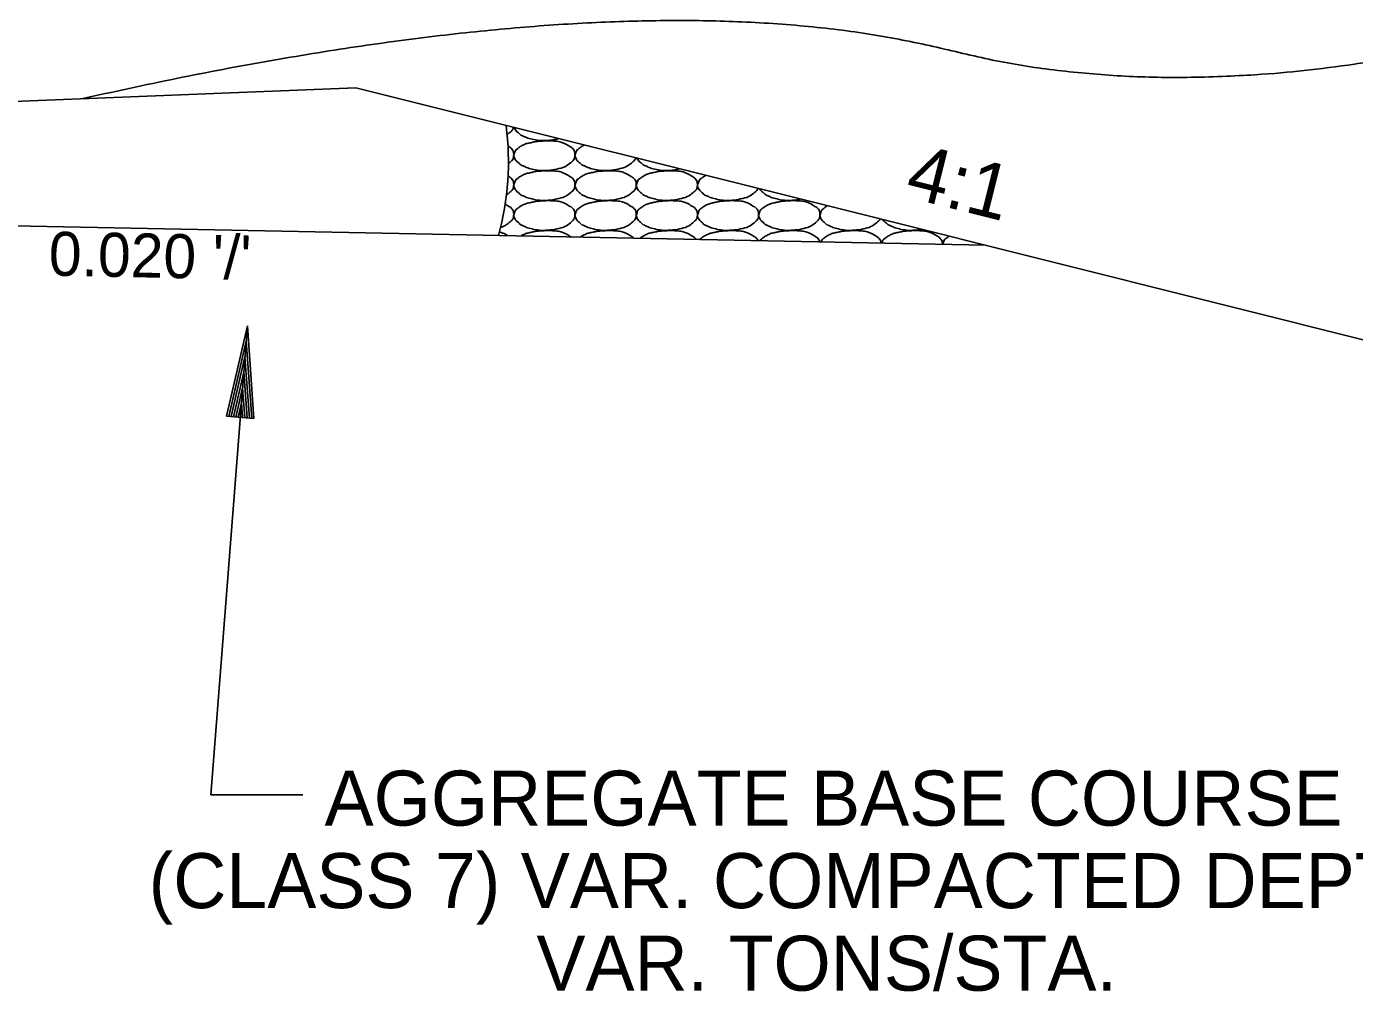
# Model space of a CAD drawing. Extents: x 2263886 to 2266026, y -3122850 to -3121850.
# Drawn here: x 2265622.12 to 2265636.6, y -3122515.03 to -3122504.51 of the extents above; entities that cross this region are included whole.
import ezdxf

# ---------------------------------------------------------------- set-up
doc = ezdxf.new("R2010")
doc.units = 0
doc.layers.add('R_Border Prem', color=7, linetype='Continuous')

msp = doc.modelspace()

# ---------------------------------------------------------------- linework, layer by layer
at = {"layer": 'R_Border Prem'}
for p, q in [((2265619.716, -3122505.418), (2265625.711, -3122505.178)), ((2265631.356, -3122506.589), (2265625.711, -3122505.178)), ((2265619.773, -3122506.638), (2265632.576, -3122506.894)), ((2265637.711, -3122508.178), (2265631.356, -3122506.589)), ((2265624.528, -3122507.774), (2265624.131, -3122512.886)), ((2265624.301, -3122508.759), (2265624.528, -3122507.774)), ((2265624.6, -3122508.782), (2265624.528, -3122507.774)), ((2265624.326, -3122508.761), (2265624.515, -3122507.94)), ((2265624.575, -3122508.78), (2265624.515, -3122507.94)), ((2265624.352, -3122508.763), (2265624.502, -3122508.112)), ((2265624.55, -3122508.778), (2265624.502, -3122508.112)), ((2265624.377, -3122508.765), (2265624.489, -3122508.278)), ((2265624.525, -3122508.777), (2265624.489, -3122508.278)), ((2265624.402, -3122508.767), (2265624.476, -3122508.447)), ((2265624.5, -3122508.775), (2265624.476, -3122508.447)), ((2265624.427, -3122508.769), (2265624.463, -3122508.613)), ((2265624.474, -3122508.773), (2265624.463, -3122508.613)), ((2265624.301, -3122508.759), (2265624.6, -3122508.782)), ((2265624.131, -3122512.886), (2265625.131, -3122512.886))]:
    msp.add_line(p, q, dxfattribs=at)
msp.add_arc((2265624.375, -3122505.984), 3, 344.4638, 7.5551, dxfattribs=at)
for points, degree in [([(2265622.714, -3122505.298), (2265628.831, -3122503.917), (2265635.52, -3122505.616), (2265640.146, -3122504.036)], 2), ([(2265627.36, -3122505.688), (2265627.369, -3122505.681), (2265627.393, -3122505.662), (2265627.421, -3122505.638), (2265627.428, -3122505.615), (2265627.429, -3122505.61)], 3), ([(2265627.439, -3122505.612), (2265627.442, -3122505.62), (2265627.449, -3122505.635), (2265627.467, -3122505.657), (2265627.492, -3122505.672), (2265627.507, -3122505.695), (2265627.534, -3122505.7), (2265627.569, -3122505.721), (2265627.631, -3122505.737), (2265627.711, -3122505.754), (2265627.806, -3122505.752), (2265627.875, -3122505.742), (2265627.913, -3122505.734), (2265627.919, -3122505.732)], 3), ([(2265627.459, -3122505.85), (2265627.453, -3122505.856), (2265627.446, -3122505.871), (2265627.439, -3122505.894), (2265627.429, -3122505.915), (2265627.439, -3122505.939), (2265627.448, -3122505.96), (2265627.467, -3122505.983), (2265627.492, -3122505.998), (2265627.507, -3122506.021), (2265627.534, -3122506.026), (2265627.569, -3122506.047), (2265627.631, -3122506.063), (2265627.711, -3122506.08), (2265627.806, -3122506.079), (2265627.904, -3122506.065), (2265627.994, -3122506.041), (2265628.053, -3122505.995), (2265628.095, -3122505.959), (2265628.1, -3122505.92), (2265628.101, -3122505.887), (2265628.093, -3122505.859), (2265628.076, -3122505.839), (2265628.059, -3122505.823), (2265628.033, -3122505.812), (2265628.011, -3122505.793), (2265627.978, -3122505.782), (2265627.938, -3122505.762), (2265627.872, -3122505.758), (2265627.801, -3122505.753), (2265627.731, -3122505.76), (2265627.676, -3122505.76), (2265627.63, -3122505.774), (2265627.584, -3122505.781), (2265627.541, -3122505.796), (2265627.502, -3122505.818), (2265627.476, -3122505.839), (2265627.458, -3122505.851), (2265627.453, -3122505.856)], 3), ([(2265627.374, -3122506.003), (2265627.379, -3122506), (2265627.398, -3122505.984), (2265627.427, -3122505.959), (2265627.432, -3122505.92), (2265627.433, -3122505.887), (2265627.425, -3122505.859), (2265627.408, -3122505.839), (2265627.391, -3122505.823), (2265627.377, -3122505.816), (2265627.369, -3122505.811)], 3), ([(2265628.127, -3122505.85), (2265628.121, -3122505.856), (2265628.113, -3122505.871), (2265628.107, -3122505.894), (2265628.097, -3122505.915), (2265628.107, -3122505.939), (2265628.116, -3122505.96), (2265628.135, -3122505.983), (2265628.16, -3122505.998), (2265628.175, -3122506.021), (2265628.202, -3122506.026), (2265628.236, -3122506.047), (2265628.299, -3122506.063), (2265628.379, -3122506.08), (2265628.474, -3122506.079), (2265628.572, -3122506.065), (2265628.662, -3122506.041), (2265628.721, -3122505.995), (2265628.754, -3122505.966), (2265628.762, -3122505.946), (2265628.763, -3122505.943)], 3), ([(2265628.199, -3122505.802), (2265628.19, -3122505.806), (2265628.168, -3122505.819), (2265628.144, -3122505.839), (2265628.126, -3122505.851), (2265628.121, -3122505.856)], 3), ([(2265627.459, -3122506.177), (2265627.453, -3122506.182), (2265627.446, -3122506.197), (2265627.439, -3122506.22), (2265627.429, -3122506.241), (2265627.439, -3122506.265), (2265627.448, -3122506.286), (2265627.467, -3122506.31), (2265627.492, -3122506.324), (2265627.507, -3122506.347), (2265627.534, -3122506.353), (2265627.569, -3122506.373), (2265627.631, -3122506.389), (2265627.711, -3122506.406), (2265627.806, -3122506.405), (2265627.904, -3122506.391), (2265627.994, -3122506.367), (2265628.053, -3122506.321), (2265628.095, -3122506.285), (2265628.1, -3122506.246), (2265628.101, -3122506.213), (2265628.093, -3122506.185), (2265628.076, -3122506.165), (2265628.059, -3122506.149), (2265628.033, -3122506.138), (2265628.011, -3122506.12), (2265627.978, -3122506.108), (2265627.938, -3122506.088), (2265627.872, -3122506.084), (2265627.801, -3122506.079), (2265627.731, -3122506.086), (2265627.676, -3122506.086), (2265627.63, -3122506.1), (2265627.584, -3122506.107), (2265627.541, -3122506.123), (2265627.502, -3122506.144), (2265627.476, -3122506.165), (2265627.458, -3122506.177), (2265627.453, -3122506.183)], 3), ([(2265628.127, -3122506.177), (2265628.121, -3122506.182), (2265628.113, -3122506.197), (2265628.107, -3122506.22), (2265628.097, -3122506.241), (2265628.107, -3122506.265), (2265628.116, -3122506.286), (2265628.135, -3122506.31), (2265628.16, -3122506.324), (2265628.175, -3122506.347), (2265628.202, -3122506.353), (2265628.236, -3122506.373), (2265628.299, -3122506.389), (2265628.379, -3122506.406), (2265628.474, -3122506.405), (2265628.572, -3122506.391), (2265628.662, -3122506.367), (2265628.721, -3122506.321), (2265628.763, -3122506.285), (2265628.768, -3122506.246), (2265628.768, -3122506.213), (2265628.761, -3122506.185), (2265628.744, -3122506.165), (2265628.727, -3122506.149), (2265628.701, -3122506.138), (2265628.678, -3122506.12), (2265628.646, -3122506.108), (2265628.606, -3122506.088), (2265628.54, -3122506.084), (2265628.469, -3122506.079), (2265628.399, -3122506.086), (2265628.344, -3122506.086), (2265628.297, -3122506.1), (2265628.252, -3122506.107), (2265628.209, -3122506.123), (2265628.17, -3122506.144), (2265628.144, -3122506.165), (2265628.126, -3122506.177), (2265628.121, -3122506.183)], 3), ([(2265628.795, -3122506.177), (2265628.789, -3122506.182), (2265628.781, -3122506.197), (2265628.775, -3122506.22), (2265628.764, -3122506.241), (2265628.775, -3122506.265), (2265628.784, -3122506.286), (2265628.803, -3122506.31), (2265628.828, -3122506.324), (2265628.843, -3122506.347), (2265628.87, -3122506.353), (2265628.904, -3122506.373), (2265628.967, -3122506.389), (2265629.047, -3122506.406), (2265629.142, -3122506.405), (2265629.24, -3122506.391), (2265629.33, -3122506.367), (2265629.389, -3122506.321), (2265629.431, -3122506.285), (2265629.436, -3122506.246), (2265629.436, -3122506.213), (2265629.428, -3122506.185), (2265629.412, -3122506.165), (2265629.394, -3122506.149), (2265629.368, -3122506.138), (2265629.346, -3122506.12), (2265629.314, -3122506.108), (2265629.273, -3122506.088), (2265629.207, -3122506.084), (2265629.137, -3122506.079), (2265629.066, -3122506.086), (2265629.012, -3122506.086), (2265628.965, -3122506.1), (2265628.92, -3122506.107), (2265628.877, -3122506.123), (2265628.838, -3122506.144), (2265628.812, -3122506.165), (2265628.794, -3122506.177), (2265628.789, -3122506.183)], 3), ([(2265628.778, -3122505.947), (2265628.78, -3122505.952), (2265628.787, -3122505.964), (2265628.803, -3122505.983), (2265628.828, -3122505.998), (2265628.843, -3122506.021), (2265628.87, -3122506.026), (2265628.904, -3122506.047), (2265628.967, -3122506.063), (2265629.047, -3122506.08), (2265629.142, -3122506.079), (2265629.205, -3122506.069), (2265629.238, -3122506.062), (2265629.238, -3122506.062)], 3), ([(2265627.354, -3122506.344), (2265627.365, -3122506.337), (2265627.392, -3122506.316), (2265627.427, -3122506.285), (2265627.432, -3122506.246), (2265627.433, -3122506.213), (2265627.425, -3122506.185), (2265627.408, -3122506.165), (2265627.392, -3122506.15), (2265627.377, -3122506.142), (2265627.37, -3122506.138)], 3), ([(2265629.463, -3122506.177), (2265629.457, -3122506.182), (2265629.449, -3122506.197), (2265629.443, -3122506.22), (2265629.432, -3122506.241), (2265629.442, -3122506.265), (2265629.452, -3122506.286), (2265629.471, -3122506.31), (2265629.495, -3122506.324), (2265629.511, -3122506.347), (2265629.538, -3122506.353), (2265629.572, -3122506.373), (2265629.634, -3122506.389), (2265629.715, -3122506.406), (2265629.81, -3122506.405), (2265629.908, -3122506.391), (2265629.998, -3122506.367), (2265630.057, -3122506.321), (2265630.087, -3122506.295), (2265630.096, -3122506.277), (2265630.096, -3122506.277)], 3), ([(2265629.524, -3122506.134), (2265629.519, -3122506.136), (2265629.501, -3122506.147), (2265629.479, -3122506.165), (2265629.462, -3122506.177), (2265629.457, -3122506.183)], 3), ([(2265630.118, -3122506.282), (2265630.119, -3122506.284), (2265630.124, -3122506.293), (2265630.139, -3122506.31), (2265630.163, -3122506.324), (2265630.179, -3122506.347), (2265630.206, -3122506.353), (2265630.24, -3122506.373), (2265630.302, -3122506.389), (2265630.383, -3122506.406), (2265630.472, -3122506.405), (2265630.53, -3122506.397), (2265630.557, -3122506.392)], 3), ([(2265627.288, -3122506.7), (2265627.302, -3122506.695), (2265627.34, -3122506.682), (2265627.385, -3122506.647), (2265627.427, -3122506.611), (2265627.432, -3122506.573), (2265627.433, -3122506.539), (2265627.425, -3122506.511), (2265627.408, -3122506.492), (2265627.391, -3122506.475), (2265627.365, -3122506.464), (2265627.35, -3122506.448), (2265627.339, -3122506.445), (2265627.339, -3122506.444)], 3), ([(2265627.459, -3122506.503), (2265627.453, -3122506.508), (2265627.446, -3122506.523), (2265627.439, -3122506.547), (2265627.429, -3122506.567), (2265627.439, -3122506.591), (2265627.448, -3122506.612), (2265627.467, -3122506.636), (2265627.492, -3122506.651), (2265627.507, -3122506.674), (2265627.534, -3122506.679), (2265627.569, -3122506.699), (2265627.631, -3122506.716), (2265627.711, -3122506.733), (2265627.806, -3122506.731), (2265627.904, -3122506.718), (2265627.994, -3122506.694), (2265628.053, -3122506.647), (2265628.095, -3122506.611), (2265628.1, -3122506.573), (2265628.101, -3122506.539), (2265628.093, -3122506.511), (2265628.076, -3122506.492), (2265628.059, -3122506.475), (2265628.033, -3122506.464), (2265628.011, -3122506.446), (2265627.978, -3122506.434), (2265627.938, -3122506.414), (2265627.872, -3122506.41), (2265627.801, -3122506.405), (2265627.731, -3122506.412), (2265627.676, -3122506.413), (2265627.63, -3122506.426), (2265627.584, -3122506.433), (2265627.541, -3122506.449), (2265627.502, -3122506.47), (2265627.476, -3122506.491), (2265627.458, -3122506.503), (2265627.453, -3122506.509)], 3), ([(2265628.127, -3122506.503), (2265628.121, -3122506.508), (2265628.113, -3122506.523), (2265628.107, -3122506.547), (2265628.097, -3122506.567), (2265628.107, -3122506.591), (2265628.116, -3122506.612), (2265628.135, -3122506.636), (2265628.16, -3122506.651), (2265628.175, -3122506.674), (2265628.202, -3122506.679), (2265628.236, -3122506.699), (2265628.299, -3122506.716), (2265628.379, -3122506.733), (2265628.474, -3122506.731), (2265628.572, -3122506.718), (2265628.662, -3122506.694), (2265628.721, -3122506.647), (2265628.763, -3122506.611), (2265628.768, -3122506.573), (2265628.768, -3122506.539), (2265628.761, -3122506.511), (2265628.744, -3122506.492), (2265628.727, -3122506.475), (2265628.701, -3122506.464), (2265628.678, -3122506.446), (2265628.646, -3122506.434), (2265628.606, -3122506.414), (2265628.54, -3122506.41), (2265628.469, -3122506.405), (2265628.399, -3122506.412), (2265628.344, -3122506.413), (2265628.297, -3122506.426), (2265628.252, -3122506.433), (2265628.209, -3122506.449), (2265628.17, -3122506.47), (2265628.144, -3122506.491), (2265628.126, -3122506.503), (2265628.121, -3122506.509)], 3), ([(2265628.795, -3122506.503), (2265628.789, -3122506.508), (2265628.781, -3122506.523), (2265628.775, -3122506.547), (2265628.764, -3122506.567), (2265628.775, -3122506.591), (2265628.784, -3122506.612), (2265628.803, -3122506.636), (2265628.828, -3122506.651), (2265628.843, -3122506.674), (2265628.87, -3122506.679), (2265628.904, -3122506.699), (2265628.967, -3122506.716), (2265629.047, -3122506.733), (2265629.142, -3122506.731), (2265629.24, -3122506.718), (2265629.33, -3122506.694), (2265629.389, -3122506.647), (2265629.431, -3122506.611), (2265629.436, -3122506.573), (2265629.436, -3122506.539), (2265629.428, -3122506.511), (2265629.412, -3122506.492), (2265629.394, -3122506.475), (2265629.368, -3122506.464), (2265629.346, -3122506.446), (2265629.314, -3122506.434), (2265629.273, -3122506.414), (2265629.207, -3122506.41), (2265629.137, -3122506.405), (2265629.066, -3122506.412), (2265629.012, -3122506.413), (2265628.965, -3122506.426), (2265628.92, -3122506.433), (2265628.877, -3122506.449), (2265628.838, -3122506.47), (2265628.812, -3122506.491), (2265628.794, -3122506.503), (2265628.789, -3122506.509)], 3), ([(2265629.463, -3122506.503), (2265629.457, -3122506.508), (2265629.449, -3122506.523), (2265629.443, -3122506.547), (2265629.432, -3122506.567), (2265629.442, -3122506.591), (2265629.452, -3122506.612), (2265629.471, -3122506.636), (2265629.495, -3122506.651), (2265629.511, -3122506.674), (2265629.538, -3122506.679), (2265629.572, -3122506.699), (2265629.634, -3122506.716), (2265629.715, -3122506.733), (2265629.81, -3122506.731), (2265629.908, -3122506.718), (2265629.998, -3122506.694), (2265630.057, -3122506.647), (2265630.099, -3122506.611), (2265630.103, -3122506.573), (2265630.104, -3122506.539), (2265630.096, -3122506.511), (2265630.08, -3122506.492), (2265630.062, -3122506.475), (2265630.036, -3122506.464), (2265630.014, -3122506.446), (2265629.982, -3122506.434), (2265629.941, -3122506.414), (2265629.875, -3122506.41), (2265629.805, -3122506.405), (2265629.734, -3122506.412), (2265629.68, -3122506.413), (2265629.633, -3122506.426), (2265629.588, -3122506.433), (2265629.545, -3122506.449), (2265629.505, -3122506.47), (2265629.479, -3122506.491), (2265629.462, -3122506.503), (2265629.457, -3122506.509)], 3), ([(2265630.131, -3122506.503), (2265630.125, -3122506.508), (2265630.117, -3122506.523), (2265630.111, -3122506.547), (2265630.1, -3122506.567), (2265630.11, -3122506.591), (2265630.12, -3122506.612), (2265630.139, -3122506.636), (2265630.163, -3122506.651), (2265630.179, -3122506.674), (2265630.206, -3122506.679), (2265630.24, -3122506.699), (2265630.302, -3122506.716), (2265630.383, -3122506.733), (2265630.478, -3122506.731), (2265630.576, -3122506.718), (2265630.665, -3122506.694), (2265630.725, -3122506.647), (2265630.767, -3122506.611), (2265630.771, -3122506.573), (2265630.772, -3122506.539), (2265630.764, -3122506.511), (2265630.748, -3122506.492), (2265630.73, -3122506.475), (2265630.704, -3122506.464), (2265630.682, -3122506.446), (2265630.649, -3122506.434), (2265630.609, -3122506.414), (2265630.543, -3122506.41), (2265630.473, -3122506.405), (2265630.402, -3122506.412), (2265630.348, -3122506.413), (2265630.301, -3122506.426), (2265630.256, -3122506.433), (2265630.212, -3122506.449), (2265630.173, -3122506.47), (2265630.147, -3122506.491), (2265630.129, -3122506.503), (2265630.125, -3122506.509)], 3), ([(2265630.799, -3122506.503), (2265630.793, -3122506.508), (2265630.785, -3122506.523), (2265630.778, -3122506.547), (2265630.768, -3122506.567), (2265630.778, -3122506.591), (2265630.788, -3122506.612), (2265630.807, -3122506.636), (2265630.831, -3122506.651), (2265630.847, -3122506.674), (2265630.874, -3122506.679), (2265630.908, -3122506.699), (2265630.97, -3122506.716), (2265631.051, -3122506.733), (2265631.145, -3122506.731), (2265631.244, -3122506.718), (2265631.333, -3122506.694), (2265631.391, -3122506.648), (2265631.419, -3122506.624), (2265631.428, -3122506.61)], 3), ([(2265630.85, -3122506.465), (2265630.849, -3122506.466), (2265630.834, -3122506.475), (2265630.815, -3122506.491), (2265630.797, -3122506.503), (2265630.793, -3122506.509)], 3), ([(2265631.459, -3122506.617), (2265631.463, -3122506.623), (2265631.476, -3122506.637), (2265631.499, -3122506.651), (2265631.515, -3122506.674), (2265631.541, -3122506.679), (2265631.576, -3122506.699), (2265631.638, -3122506.716), (2265631.718, -3122506.733), (2265631.802, -3122506.731), (2265631.853, -3122506.725), (2265631.874, -3122506.721)], 3), ([(2265627.369, -3122506.79), (2265627.369, -3122506.79), (2265627.359, -3122506.784), (2265627.343, -3122506.772), (2265627.311, -3122506.761), (2265627.29, -3122506.753), (2265627.276, -3122506.748)], 3), ([(2265628.061, -3122506.804), (2265628.06, -3122506.803), (2265628.052, -3122506.798), (2265628.033, -3122506.79), (2265628.011, -3122506.772), (2265627.978, -3122506.76), (2265627.938, -3122506.741), (2265627.872, -3122506.736), (2265627.801, -3122506.732), (2265627.731, -3122506.738), (2265627.676, -3122506.739), (2265627.63, -3122506.752), (2265627.584, -3122506.759), (2265627.542, -3122506.775), (2265627.517, -3122506.787), (2265627.509, -3122506.793)], 3), ([(2265628.744, -3122506.817), (2265628.739, -3122506.812), (2265628.726, -3122506.801), (2265628.701, -3122506.79), (2265628.678, -3122506.772), (2265628.646, -3122506.76), (2265628.606, -3122506.741), (2265628.54, -3122506.736), (2265628.469, -3122506.732), (2265628.399, -3122506.738), (2265628.344, -3122506.739), (2265628.297, -3122506.752), (2265628.252, -3122506.759), (2265628.209, -3122506.775), (2265628.177, -3122506.792), (2265628.163, -3122506.802), (2265628.158, -3122506.806)], 3), ([(2265629.423, -3122506.831), (2265629.42, -3122506.827), (2265629.411, -3122506.817), (2265629.394, -3122506.802), (2265629.368, -3122506.79), (2265629.346, -3122506.772), (2265629.314, -3122506.76), (2265629.273, -3122506.741), (2265629.207, -3122506.736), (2265629.137, -3122506.732), (2265629.066, -3122506.738), (2265629.012, -3122506.739), (2265628.965, -3122506.752), (2265628.92, -3122506.759), (2265628.877, -3122506.775), (2265628.839, -3122506.796), (2265628.819, -3122506.81), (2265628.808, -3122506.819)], 3), ([(2265630.097, -3122506.844), (2265630.096, -3122506.841), (2265630.092, -3122506.831), (2265630.08, -3122506.818), (2265630.062, -3122506.802), (2265630.036, -3122506.79), (2265630.014, -3122506.772), (2265629.982, -3122506.76), (2265629.941, -3122506.741), (2265629.875, -3122506.736), (2265629.805, -3122506.732), (2265629.734, -3122506.738), (2265629.68, -3122506.739), (2265629.633, -3122506.752), (2265629.588, -3122506.759), (2265629.545, -3122506.775), (2265629.505, -3122506.796), (2265629.48, -3122506.816), (2265629.464, -3122506.828), (2265629.46, -3122506.832)], 3), ([(2265630.769, -3122506.858), (2265630.768, -3122506.85), (2265630.762, -3122506.835), (2265630.748, -3122506.818), (2265630.73, -3122506.802), (2265630.704, -3122506.79), (2265630.682, -3122506.772), (2265630.649, -3122506.76), (2265630.609, -3122506.741), (2265630.543, -3122506.736), (2265630.473, -3122506.732), (2265630.402, -3122506.738), (2265630.348, -3122506.739), (2265630.301, -3122506.752), (2265630.256, -3122506.759), (2265630.212, -3122506.775), (2265630.173, -3122506.796), (2265630.147, -3122506.817), (2265630.129, -3122506.829), (2265630.125, -3122506.835)], 3), ([(2265631.439, -3122506.871), (2265631.439, -3122506.87), (2265631.438, -3122506.857), (2265631.432, -3122506.837), (2265631.416, -3122506.818), (2265631.398, -3122506.802), (2265631.372, -3122506.79), (2265631.35, -3122506.772), (2265631.317, -3122506.76), (2265631.277, -3122506.741), (2265631.211, -3122506.736), (2265631.141, -3122506.732), (2265631.07, -3122506.738), (2265631.016, -3122506.739), (2265630.969, -3122506.752), (2265630.923, -3122506.759), (2265630.88, -3122506.775), (2265630.841, -3122506.796), (2265630.815, -3122506.817), (2265630.797, -3122506.829), (2265630.793, -3122506.835)], 3), ([(2265632.107, -3122506.885), (2265632.107, -3122506.879), (2265632.107, -3122506.861), (2265632.1, -3122506.837), (2265632.083, -3122506.818), (2265632.066, -3122506.802), (2265632.04, -3122506.79), (2265632.018, -3122506.772), (2265631.985, -3122506.76), (2265631.945, -3122506.741), (2265631.879, -3122506.736), (2265631.808, -3122506.732), (2265631.738, -3122506.738), (2265631.684, -3122506.739), (2265631.637, -3122506.752), (2265631.591, -3122506.759), (2265631.548, -3122506.775), (2265631.509, -3122506.796), (2265631.483, -3122506.817), (2265631.465, -3122506.829), (2265631.461, -3122506.835)], 3), ([(2265632.177, -3122506.797), (2265632.166, -3122506.804), (2265632.15, -3122506.818), (2265632.133, -3122506.829), (2265632.128, -3122506.835)], 3), ([(2265629.463, -3122506.829), (2265629.462, -3122506.83), (2265629.461, -3122506.831), (2265629.46, -3122506.832)], 3), ([(2265630.131, -3122506.829), (2265630.126, -3122506.833), (2265630.122, -3122506.839), (2265630.119, -3122506.845)], 3), ([(2265630.799, -3122506.829), (2265630.793, -3122506.834), (2265630.787, -3122506.845), (2265630.783, -3122506.856), (2265630.782, -3122506.858)], 3), ([(2265631.467, -3122506.829), (2265631.46, -3122506.834), (2265631.453, -3122506.849), (2265631.448, -3122506.864), (2265631.446, -3122506.871), (2265631.446, -3122506.871)], 3), ([(2265632.134, -3122506.829), (2265632.128, -3122506.834), (2265632.121, -3122506.849), (2265632.115, -3122506.869), (2265632.112, -3122506.88), (2265632.111, -3122506.885)], 3)]:
    msp.add_open_spline(points, degree=degree, dxfattribs=at)

# ---------------------------------------------------------------- texts
for s, height, rotation, p in [('4:1', 0.6, 345.9638, (2265631.683, -3122506.362)), ("0.020 '/'", 0.48, 358.854, (2265622.359, -3122507.224))]:
    msp.add_text(s, height=height, rotation=rotation, dxfattribs=at).set_placement(p)
for s, p in [('AGGREGATE BASE COURSE', (2265625.37, -3122513.223)), ('(CLASS 7) VAR. COMPACTED DEPTH', (2265623.452, -3122514.123)), ('VAR. TONS/STA.', (2265627.68, -3122515.023))]:
    msp.add_text(s, height=0.6, dxfattribs=at).set_placement(p)

doc.saveas('drawing.dxf')
